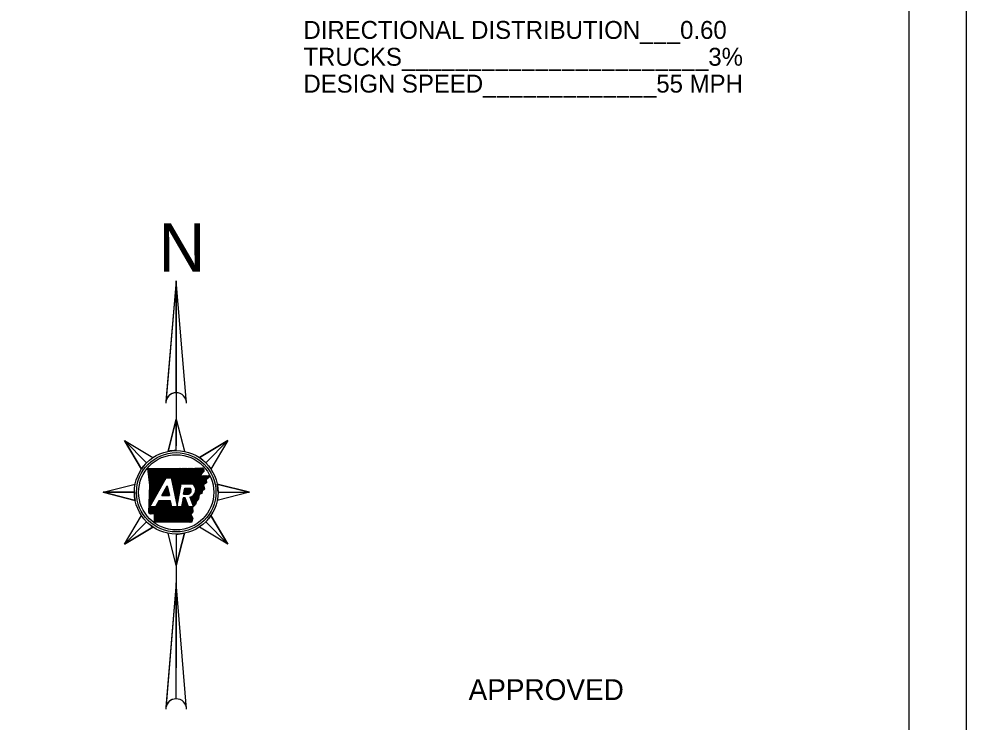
# Model space of a CAD drawing. Extents: x 1370567 to 1373900, y 377514 to 379648.
# Drawn here: x 1373107 to 1373900, y 377995 to 378584 of the extents above; entities that cross this region are included whole.
import ezdxf

# ---------------------------------------------------------------- set-up
doc = ezdxf.new("R2010")
doc.units = 0
for name, color, linetype in [('S_EXIST_ROW', 7, 'Continuous'), ('S_EXISTING_ALIGNMENT_ANNOT', 7, 'Continuous'), ('S_SIXTEEN_SECTION', 7, 'Continuous'), ('Survey Names', 7, 'Continuous'), ('Survey Symbols', 7, 'Continuous')]:
    doc.layers.add(name, color=color, linetype=linetype)

msp = doc.modelspace()

# ---------------------------------------------------------------- linework, layer by layer
at = {"layer": 'S_EXISTING_ALIGNMENT_ANNOT'}
for p, q in [((1373215, 378207.52), (1373215.31, 378207.83)), ((1373215.11, 378206.64), (1373216.3, 378207.83)), ((1373215.22, 378205.76), (1373217.29, 378207.82)), ((1373215.33, 378204.88), (1373218.28, 378207.82)), ((1373215.44, 378204), (1373219.27, 378207.82)), ((1373215.55, 378203.12), (1373220.26, 378207.82)), ((1373215.66, 378202.24), (1373221.25, 378207.82)), ((1373215.77, 378201.35), (1373222.24, 378207.82)), ((1373215.88, 378200.47), (1373223.23, 378207.82)), ((1373215.99, 378199.59), (1373224.22, 378207.82)), ((1373216.1, 378198.71), (1373225.21, 378207.82)), ((1373216.21, 378197.83), (1373226.2, 378207.82)), ((1373216.32, 378196.95), (1373227.19, 378207.82)), ((1373216.43, 378196.07), (1373228.17, 378207.82)), ((1373216.46, 378186.21), (1373238.09, 378207.84)), ((1373216.5, 378187.23), (1373237.1, 378207.84)), ((1373216.53, 378188.25), (1373236.11, 378207.83)), ((1373216.54, 378195.19), (1373229.17, 378207.82)), ((1373216.56, 378189.28), (1373235.12, 378207.83)), ((1373216.6, 378190.3), (1373234.13, 378207.83)), ((1373216.63, 378191.33), (1373233.13, 378207.83)), ((1373216.65, 378194.31), (1373230.16, 378207.82)), ((1373216.67, 378192.35), (1373232.14, 378207.82)), ((1373216.7, 378193.37), (1373231.15, 378207.82)), ((1373231.16, 378199.92), (1373239.09, 378207.84)), ((1373232.15, 378199.92), (1373240.08, 378207.84)), ((1373233.14, 378199.92), (1373241.08, 378207.85)), ((1373234.13, 378199.92), (1373242.08, 378207.87)), ((1373234.75, 378199.54), (1373243.09, 378207.88)), ((1373234.92, 378198.73), (1373244.09, 378207.9)), ((1373235.1, 378197.91), (1373245.1, 378207.91)), ((1373235.27, 378197.1), (1373246.1, 378207.93)), ((1373235.45, 378196.28), (1373247.11, 378207.94)), ((1373235.62, 378195.47), (1373248.12, 378207.96)), ((1373235.8, 378194.65), (1373249.12, 378207.97)), ((1373235.97, 378193.84), (1373250.13, 378207.99)), ((1373236.15, 378193.02), (1373251.13, 378208.01)), ((1373236.32, 378192.2), (1373252.14, 378208.02)), ((1373236.5, 378191.39), (1373253.14, 378208.04)), ((1373236.67, 378190.57), (1373254.15, 378208.05)), ((1373236.84, 378189.76), (1373255.16, 378208.07)), ((1373237.02, 378188.94), (1373256.17, 378208.1)), ((1373243.9, 378194.83), (1373257.18, 378208.12)), ((1373244.89, 378194.83), (1373258.2, 378208.14)), ((1373245.88, 378194.83), (1373259.21, 378208.17)), ((1373246.87, 378194.83), (1373260.22, 378208.19)), ((1373247.86, 378194.83), (1373261.24, 378208.21)), ((1373248.85, 378194.83), (1373261.46, 378207.44)), ((1373249.84, 378194.83), (1373261.94, 378206.93)), ((1373250.83, 378194.83), (1373262.07, 378206.07)), ((1373251.82, 378194.83), (1373259.8, 378202.82)), ((1373252.71, 378194.74), (1373259.61, 378201.64)), ((1373253.25, 378194.29), (1373260.65, 378201.69)), ((1373253.74, 378193.78), (1373261.7, 378201.74)), ((1373254.17, 378193.22), (1373262.74, 378201.8)), ((1373254.53, 378192.6), (1373263.78, 378201.85)), ((1373254.84, 378191.91), (1373264.83, 378201.9)), ((1373255.06, 378191.15), (1373265.77, 378201.85)), ((1373255.2, 378190.29), (1373266.23, 378201.33)), ((1373265.79, 378199.9), (1373266.69, 378200.8)), ((1373216.36, 378183.13), (1373227.2, 378193.98)), ((1373216.39, 378184.16), (1373228.49, 378196.26)), ((1373216.43, 378185.18), (1373229.79, 378198.54)), ((1373230.73, 378191.84), (1373231.53, 378192.64)), ((1373237.19, 378188.13), (1373242.81, 378193.75)), ((1373250.91, 378182.04), (1373261.88, 378193.02)), ((1373254.14, 378186.26), (1373261.7, 378193.82)), ((1373255, 378188.11), (1373263.98, 378197.1)), ((1373255.2, 378189.31), (1373263.87, 378197.97)), ((1373262.87, 378195), (1373264.1, 378196.22)), ((1373216.23, 378179.04), (1373222.03, 378184.85)), ((1373216.26, 378180.06), (1373223.33, 378187.13)), ((1373216.29, 378181.09), (1373224.62, 378189.41)), ((1373216.33, 378182.11), (1373225.91, 378191.69)), ((1373226.96, 378185.1), (1373232.05, 378190.19)), ((1373227.95, 378185.1), (1373232.23, 378189.37)), ((1373228.15, 378187.27), (1373231.88, 378191)), ((1373228.94, 378185.1), (1373232.4, 378188.56)), ((1373229.44, 378189.56), (1373231.7, 378191.82)), ((1373229.93, 378185.1), (1373232.57, 378187.74)), ((1373230.92, 378185.1), (1373232.75, 378186.93)), ((1373231.91, 378185.1), (1373232.92, 378186.11)), ((1373232.9, 378185.1), (1373233.1, 378185.3)), ((1373237.37, 378187.31), (1373242.6, 378192.55)), ((1373237.54, 378186.5), (1373242.39, 378191.35)), ((1373237.72, 378185.68), (1373242.18, 378190.15)), ((1373237.89, 378184.87), (1373241.97, 378188.95)), ((1373238.07, 378184.05), (1373241.77, 378187.75)), ((1373238.24, 378183.24), (1373241.56, 378186.55)), ((1373238.41, 378182.42), (1373241.35, 378185.35)), ((1373245.09, 378186.18), (1373250.29, 378191.39)), ((1373245.29, 378187.37), (1373249.3, 378191.39)), ((1373245.5, 378188.57), (1373248.31, 378191.39)), ((1373245.71, 378189.77), (1373247.33, 378191.39)), ((1373245.92, 378190.97), (1373246.34, 378191.39)), ((1373246.08, 378186.18), (1373250.85, 378190.95)), ((1373247.07, 378186.18), (1373251.18, 378190.29)), ((1373248.06, 378186.18), (1373251.36, 378189.49)), ((1373249.05, 378186.18), (1373251.28, 378188.41)), ((1373251.18, 378181.32), (1373262.07, 378192.21)), ((1373251.44, 378180.6), (1373262.25, 378191.41)), ((1373251.71, 378179.88), (1373262.44, 378190.61)), ((1373251.98, 378179.15), (1373257.92, 378185.09)), ((1373259.06, 378186.23), (1373260.44, 378187.62)), ((1373216.12, 378175.97), (1373218.16, 378178)), ((1373216.16, 378176.99), (1373219.45, 378180.28)), ((1373216.19, 378178.02), (1373220.74, 378182.56)), ((1373216.34, 378170.24), (1373226.74, 378180.65)), ((1373216.93, 378169.84), (1373227.73, 378180.65)), ((1373217.64, 378169.56), (1373228.72, 378180.65)), ((1373218.81, 378169.75), (1373229.71, 378180.65)), ((1373219.82, 378169.76), (1373230.7, 378180.65)), ((1373220.59, 378169.55), (1373231.69, 378180.65)), ((1373220.63, 378167.6), (1373233.67, 378180.65)), ((1373220.63, 378168.59), (1373232.68, 378180.65)), ((1373220.63, 378166.62), (1373234.19, 378180.18)), ((1373220.63, 378165.63), (1373234.37, 378179.36)), ((1373220.64, 378164.64), (1373234.54, 378178.55)), ((1373220.64, 378163.65), (1373234.72, 378177.73)), ((1373220.66, 378162.68), (1373234.89, 378176.92)), ((1373222.62, 378177.51), (1373225.75, 378180.65)), ((1373223.91, 378179.79), (1373224.76, 378180.65)), ((1373230.54, 378162.67), (1373247.57, 378179.69)), ((1373231.53, 378162.66), (1373247.83, 378178.97)), ((1373232.52, 378162.66), (1373248.1, 378178.25)), ((1373233.5, 378162.66), (1373248.37, 378177.52)), ((1373234.49, 378162.66), (1373248.63, 378176.8)), ((1373238.59, 378181.6), (1373241.14, 378184.15)), ((1373238.76, 378180.79), (1373240.93, 378182.96)), ((1373238.94, 378179.97), (1373240.72, 378181.76)), ((1373239.11, 378179.16), (1373240.51, 378180.56)), ((1373239.29, 378178.34), (1373240.3, 378179.36)), ((1373239.46, 378177.53), (1373240.09, 378178.16)), ((1373239.64, 378176.71), (1373239.89, 378176.96)), ((1373243.4, 378176.51), (1373247.3, 378180.41)), ((1373243.6, 378177.71), (1373247.03, 378181.14)), ((1373243.81, 378178.91), (1373246.76, 378181.86)), ((1373244.02, 378180.11), (1373246.5, 378182.58)), ((1373244.23, 378181.31), (1373246.21, 378183.29)), ((1373244.44, 378182.51), (1373245.22, 378183.29)), ((1373250.38, 378183.49), (1373250.68, 378183.79)), ((1373250.64, 378182.77), (1373252.53, 378184.65)), ((1373252.24, 378178.43), (1373257.8, 378183.99)), ((1373252.51, 378177.71), (1373257.69, 378182.89)), ((1373252.78, 378176.98), (1373255.81, 378180.02)), ((1373253.05, 378176.26), (1373255.39, 378178.61)), ((1373215.97, 378170.86), (1373220.64, 378175.53)), ((1373215.99, 378171.87), (1373219.65, 378175.53)), ((1373216.02, 378172.9), (1373218.66, 378175.53)), ((1373216.06, 378173.92), (1373217.67, 378175.53)), ((1373216.09, 378174.94), (1373216.86, 378175.72)), ((1373221.64, 378162.68), (1373235.07, 378176.1)), ((1373222.63, 378162.68), (1373235.48, 378175.53)), ((1373223.62, 378162.68), (1373236.47, 378175.53)), ((1373224.61, 378162.67), (1373237.46, 378175.53)), ((1373225.6, 378162.67), (1373238.45, 378175.53)), ((1373226.59, 378162.67), (1373239.44, 378175.53)), ((1373227.57, 378162.67), (1373240.43, 378175.53)), ((1373228.56, 378162.67), (1373241.42, 378175.53)), ((1373229.55, 378162.67), (1373242.41, 378175.53)), ((1373235.48, 378162.66), (1373248.9, 378176.08)), ((1373236.47, 378162.66), (1373249.34, 378175.53)), ((1373237.46, 378162.65), (1373250.33, 378175.53)), ((1373238.45, 378162.65), (1373251.32, 378175.53)), ((1373239.43, 378162.65), (1373252.31, 378175.53)), ((1373240.42, 378162.65), (1373252.64, 378174.87)), ((1373241.41, 378162.65), (1373252.69, 378173.93)), ((1373242.4, 378162.65), (1373252.73, 378172.98)), ((1373243.39, 378162.64), (1373252.78, 378172.03)), ((1373244.38, 378162.64), (1373251.15, 378169.42)), ((1373245.36, 378162.64), (1373251.46, 378168.73)), ((1373246.35, 378162.64), (1373251.76, 378168.05)), ((1373247.34, 378162.64), (1373252.07, 378167.37)), ((1373248.33, 378162.64), (1373252.37, 378166.68)), ((1373249.32, 378162.63), (1373252.63, 378165.95)), ((1373250.31, 378162.63), (1373252.18, 378164.51)), ((1373251.29, 378162.63), (1373251.73, 378163.07))]:
    msp.add_line(p, q, dxfattribs=at)
msp.add_circle((1373238.86, 378187.79), 33.25, dxfattribs=at)
at = {"layer": 'S_SIXTEEN_SECTION'}
msp.add_line((1373852.74, 377554.33), (1373852.74, 379608.93), dxfattribs=at)
at = {"layer": 'Survey Names'}
for p, q in [((1373238.86, 378364.79), (1373230.24, 378263.9)), ((1373238.86, 378364.79), (1373238.86, 378226.61)), ((1373238.86, 378271.16), (1373238.86, 378364.79)), ((1373230.36, 378265.3), (1373230.75, 378265.7)), ((1373230.4, 378265.84), (1373231.2, 378266.64)), ((1373238.86, 378249.04), (1373232.05, 378222.12)), ((1373238.86, 378222.79), (1373238.86, 378249.04)), ((1373195.55, 378231.1), (1373214.11, 378212.54)), ((1373214.11, 378212.54), (1373195.55, 378231.1)), ((1373195.55, 378231.1), (1373209.77, 378207.25)), ((1373282.17, 378231.1), (1373258.32, 378216.88)), ((1373263.61, 378212.54), (1373282.17, 378231.1)), ((1373263.61, 378212.54), (1373282.17, 378231.1)), ((1373216.76, 378175.53), (1373230.57, 378199.92)), ((1373226.92, 378185.1), (1373231.43, 378193.08)), ((1373230.57, 378199.92), (1373234.67, 378199.92)), ((1373243, 378194.83), (1373252.59, 378194.83)), ((1373300.11, 378187.79), (1373273.19, 378194.61)), ((1373177.61, 378187.79), (1373203.86, 378187.79)), ((1373203.86, 378187.79), (1373177.61, 378187.79)), ((1373177.61, 378187.79), (1373204.53, 378180.97)), ((1373226.92, 378185.1), (1373233.14, 378185.1)), ((1373245.08, 378186.18), (1373249.19, 378186.18)), ((1373245.99, 378191.39), (1373250.49, 378191.39)), ((1373273.86, 378187.79), (1373300.11, 378187.79)), ((1373273.86, 378187.79), (1373300.11, 378187.79)), ((1373224.39, 378180.65), (1373221.5, 378175.53)), ((1373234.09, 378180.65), (1373224.39, 378180.65)), ((1373246.24, 378183.29), (1373244.58, 378183.29)), ((1373249.1, 378175.53), (1373246.24, 378183.29)), ((1373250.3, 378183.7), (1373253.32, 378175.53)), ((1373221.5, 378175.53), (1373216.76, 378175.53)), ((1373243.22, 378175.53), (1373235.19, 378175.53)), ((1373253.32, 378175.53), (1373249.1, 378175.53)), ((1373195.55, 378144.48), (1373214.11, 378163.04)), ((1373214.11, 378163.04), (1373195.55, 378144.48)), ((1373263.61, 378163.04), (1373282.17, 378144.48)), ((1373263.61, 378163.04), (1373282.17, 378144.48)), ((1373282.17, 378144.48), (1373267.96, 378168.33)), ((1373195.55, 378144.48), (1373219.41, 378158.7)), ((1373238.86, 378126.54), (1373245.68, 378153.46)), ((1373238.86, 378152.79), (1373238.86, 378152.79)), ((1373238.86, 378152.79), (1373238.86, 378040.75)), ((1373238.86, 378152.79), (1373238.86, 378126.54)), ((1373238.86, 378111.91), (1373230.23, 378007.47)), ((1373238.86, 378014.79), (1373238.86, 378111.91))]:
    msp.add_line(p, q, dxfattribs=at)
for points in [[(1373247.61, 378262.41), (1373238.86, 378364.79), (1373230.11, 378262.41)], [(1373232.05, 378222.12), (1373238.86, 378249.04), (1373245.68, 378222.12)], [(1373209.77, 378207.25), (1373195.55, 378231.1), (1373219.41, 378216.88)], [(1373258.32, 378216.88), (1373282.17, 378231.1), (1373267.96, 378207.25)], [(1373214.97, 378207.83), (1373228.62, 378207.82), (1373240.61, 378207.84), (1373254.75, 378208.06), (1373261.3, 378208.21)], [(1373215.95, 378170.87), (1373216.71, 378193.79), (1373214.97, 378207.83)], [(1373265.59, 378201.94), (1373266.77, 378200.7), (1373263.83, 378198.28), (1373264.15, 378195.84), (1373261.62, 378194.17), (1373262.48, 378190.41), (1373260.54, 378188.63), (1373260.36, 378186.7), (1373257.99, 378185.85), (1373257.62, 378182.2), (1373255.92, 378180.38), (1373255.1, 378177.64), (1373252.62, 378175.37), (1373252.81, 378171.36), (1373251.13, 378169.48), (1373252.66, 378166.04), (1373251.6, 378162.63)], [(1373259.27, 378201.62), (1373265.69, 378201.95)], [(1373204.53, 378180.97), (1373177.61, 378187.79), (1373204.53, 378194.61)], [(1373231.43, 378193.08), (1373233.14, 378185.1)], [(1373234.67, 378199.92), (1373239.75, 378176.18), (1373243, 378194.83)], [(1373273.19, 378194.61), (1373300.11, 378187.79), (1373273.19, 378180.97)], [(1373245.08, 378186.18), (1373245.99, 378191.39)], [(1373235.19, 378175.53), (1373234.09, 378180.65)], [(1373244.58, 378183.29), (1373243.22, 378175.53)], [(1373251.6, 378162.63), (1373220.64, 378162.68), (1373220.62, 378169.51)], [(1373219.41, 378158.7), (1373195.55, 378144.48), (1373209.77, 378168.33)], [(1373267.96, 378168.33), (1373282.17, 378144.48), (1373258.32, 378158.7)], [(1373245.68, 378153.46), (1373238.86, 378126.54), (1373232.05, 378153.46)], [(1373247.61, 378006.04), (1373238.86, 378111.91), (1373230.11, 378006.04)]]:
    msp.add_lwpolyline(points, dxfattribs=at)
for radius in [35, 31.5]:
    msp.add_circle((1373238.86, 378187.79), radius, dxfattribs=at)
for centre, radius, start, end in [((1373238.86, 378262.41), 8.75, 0, 180), ((1373238.86, 378262.41), 8.75, 90, 170.22959), ((1373238.86, 378187.79), 35, 90, 101.22909), ((1373238.86, 378187.79), 35, 45, 56.22909), ((1373238.86, 378187.79), 35, 135, 146.22909), ((1373249.02, 378189.76), 6.2, 281.86262, 54.87052), ((1373238.86, 378187.79), 35, 0, 11.22909), ((1373238.86, 378187.79), 35, 180, 191.22909), ((1373248.21, 378189.19), 3.17, 288.12683, 43.89016), ((1373238.86, 378187.79), 35, 225, 236.22909), ((1373238.86, 378187.79), 35, 315, 326.22909), ((1373238.86, 378187.79), 35, 270, 281.22909), ((1373238.86, 378006.04), 8.75, 0, 180), ((1373238.86, 378006.04), 8.75, 90, 170.5511)]:
    msp.add_arc(centre, radius, start, end, dxfattribs=at)
for points in [[(1373261.3, 378208.21), (1373261.34, 378207.84), (1373261.46, 378207.65), (1373261.48, 378207.29), (1373261.62, 378207.14), (1373261.87, 378206.99), (1373262.09, 378206.74), (1373262.14, 378206.46), (1373262.07, 378206.16), (1373262.05, 378205.83), (1373262.02, 378205.55), (1373261.97, 378205.28), (1373261.77, 378205.07), (1373261.57, 378204.92), (1373261.39, 378204.74), (1373261.27, 378204.56), (1373261.05, 378204.35), (1373260.83, 378204.14), (1373260.65, 378203.96), (1373260.47, 378203.72), (1373260.39, 378203.46), (1373260.2, 378203.27), (1373260.04, 378203.1), (1373259.84, 378202.88), (1373259.74, 378202.65), (1373259.54, 378202.39), (1373259.5, 378202.13), (1373259.38, 378201.93), (1373259.37, 378201.9)], [(1373220.62, 378169.51), (1373220.66, 378169.5), (1373220.5, 378169.61), (1373220.28, 378169.72), (1373220.03, 378169.73), (1373219.72, 378169.78), (1373219.46, 378169.8), (1373219.19, 378169.98), (1373218.9, 378169.79), (1373218.58, 378169.66), (1373218.4, 378169.81), (1373218.15, 378169.71), (1373217.98, 378169.76), (1373217.69, 378169.56), (1373217.41, 378169.63), (1373217.2, 378169.57), (1373216.95, 378169.58), (1373216.9, 378169.87), (1373216.66, 378169.91), (1373216.44, 378170.03), (1373216.3, 378170.33), (1373216.2, 378170.55), (1373215.95, 378170.87)]]:
    msp.add_spline(points, degree=3, dxfattribs=at)
at = {"layer": 'Survey Symbols'}
msp.add_lwpolyline([(1370566.86, 379647.87), (1373900.26, 379647.87), (1373900.26, 377514.5), (1370566.86, 377514.5)], close=True, dxfattribs=at)

# ---------------------------------------------------------------- texts
at = {"layer": 'S_EXIST_ROW'}
msp.add_text('APPROVED', height=17.496, dxfattribs=at).set_placement((1373483.7, 378013.76))
at = {"layer": 'Survey Names'}
for s, height, p in [('DIRECTIONAL DISTRIBUTION___0.60', 15, (1373345.39, 378567.59)), ('TRUCKS_______________________3%', 15, (1373345.39, 378545.09)), ('DESIGN SPEED_____________55 MPH', 15, (1373345.39, 378522.59)), ('N', 40.39, (1373224.11, 378372.73)), ('DWB 7-27-17', 0.6806, (1373236.72, 378155.71))]:
    msp.add_text(s, height=height, dxfattribs=at).set_placement(p)

doc.saveas('drawing.dxf')
